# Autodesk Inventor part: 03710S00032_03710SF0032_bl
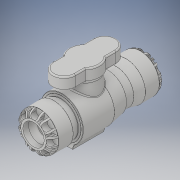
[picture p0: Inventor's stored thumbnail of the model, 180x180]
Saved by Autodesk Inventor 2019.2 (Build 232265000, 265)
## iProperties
Created: 2022-04
Part Number: 03710S00032_03710SF0032_bl
Material: Generic
Description: PA Ball Valve Series 1 32mm x 32mm
Document SubType Name: Modeling
Designer: Lenora
Density: 1 g/cm^3
Appearance: Default
Author: Lenora
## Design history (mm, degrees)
derived "037100.ipt"
feature "Solid1::037100.ipt" dims "ScaleForDerivedMember" = 10
tag "TaggingFeature1"
body "Solid1"
other parameters: "d16" = 93.5 [user parameter], "d19" = 1 [user parameter], "d20" = 42.5 [user parameter], "d22" = 85 deg [user parameter], "d25" = 1 [user parameter], "d34" = 30.6 [user parameter], "d35" = 17 [user parameter], "d37" = 0 [user parameter], "d39" = 360 deg [user parameter], "d43" = 33 [user parameter], "d45" = 70 deg [user parameter], "d46" = 70 deg [user parameter], "d48" = 0 [user parameter], "d57" = 2 [user parameter], "d58" = 32 [user parameter], "d59" = 1 [user parameter], "d60" = 25 [user parameter], "d61" = 8.5 [user parameter], "d62" = 12.75 [user parameter], "d63" = 64 [user parameter], "d65" = 51.84 [user parameter], "d66" = 89 deg [user parameter], "d67" = 30.6 [user parameter], "d69" = 42.5 [user parameter], "d70" = 1.19 [user parameter], "d71" = 8.5 [user parameter], "d72" = 12.75 [user parameter], "d73" = 30.6 [user parameter], "d76" = 64 [user parameter], "d77" = 19.2 [user parameter], "d78" = 45.9 [user parameter], "d79" = 21.25 [user parameter], "d80" = 100 deg [user parameter], "d81" = 14.45 [user parameter], "d83" = 28.05 [user parameter], "d84" = 12.75 [user parameter], "d85" = 32 [user parameter], "d90" = 0 [user parameter], "d91" = 9.6 [user parameter], "d92" = 45 deg [user parameter], "d93" = 5.12 [user parameter], "d94" = 2.048 [user parameter], "d95" = 2.56 [user parameter], "d96" = 2.56 [user parameter], "d97" = 2.56 [user parameter], "d98" = 2.56 [user parameter], "d101" = 8.96 [user parameter], "d102" = 0 [user parameter], "d104" = 360 deg [user parameter], "d106" = 8.96 [user parameter], "d107" = 0 [user parameter], "d109" = 360 deg [user parameter], "d111" = 0.5 [user parameter], "d112" = 2 [user parameter], "d113" = 58 [user parameter], "d" = 32 [user parameter], "DN" = 25 [user parameter], "A1" = 33 [user parameter], "A2" = 64 [user parameter], "E_" = 64 [user parameter], "E1" = 58 [user parameter]
